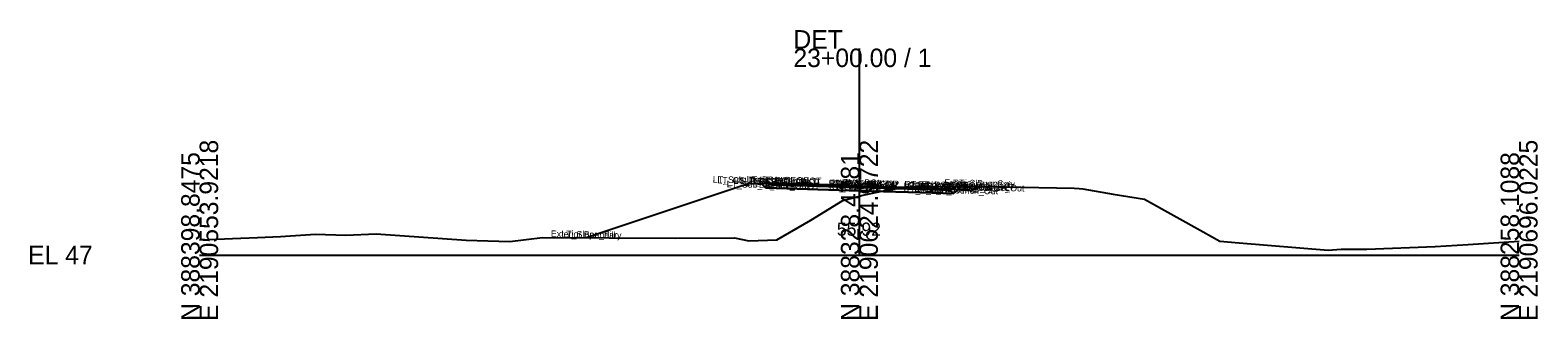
# Model space of a CAD drawing. Extents: x -26 to 1203, y -10 to 9543.
# Drawn here: x 974.3 to 1202.8, y 2990.3 to 3034.1 of the extents above; entities that cross this region are included whole.
import ezdxf

# ---------------------------------------------------------------- set-up
doc = ezdxf.new("R2010")
doc.units = 0
for name, color, linetype in [('Default', 7, 'Continuous'), ('Exist Cross Section Cell', 7, 'Continuous'), ('Exist XS Center Line Elevation Label', 7, 'Continuous'), ('Exist XS Ground Line', 7, 'Continuous'), ('Prop CMT Pvmt Course 1', 7, 'Continuous'), ('Prop CMT Pvmt Course 2', 7, 'Continuous'), ('Prop CMT Pvmt Course 3', 7, 'Continuous'), ('Prop CMT Pvmt Surface', 7, 'Continuous'), ('Prop CMT Pvmt Surface Shoulder', 7, 'Continuous'), ('Prop CMT Shld Paved Course 1', 7, 'Continuous'), ('Prop CMT Shld Paved Course 2', 7, 'Continuous'), ('Prop CMT Shld Paved Course 3', 7, 'Continuous'), ('Prop CMT Slope Grass', 7, 'Continuous'), ('Prop CMT Subgrade Earthwork', 7, 'Continuous'), ('Scratch_Level_0', 7, 'Continuous')]:
    doc.layers.add(name, color=color, linetype=linetype)

msp = doc.modelspace()

# ---------------------------------------------------------------- linework, layer by layer
at = {"layer": 'Exist Cross Section Cell'}
for p, q in [((1100, 3000), (1100, 3031.32)), ((1000, 3000), (1100, 3000)), ((1100, 3000), (1200, 3000))]:
    msp.add_line(p, q, dxfattribs=at)
at = {"layer": 'Exist XS Ground Line'}
for p, q in [((1100.34, 3009.01), (1104.09, 3009.82)), ((1104.09, 3009.82), (1105.8, 3010.08)), ((1105.8, 3010.08), (1107.76, 3010.34)), ((1107.76, 3010.34), (1108.23, 3010.39)), ((1108.23, 3010.39), (1108.58, 3010.42)), ((1108.58, 3010.42), (1109.18, 3010.42)), ((1109.18, 3010.42), (1110.22, 3010.44)), ((1110.22, 3010.44), (1121.06, 3010.36)), ((1121.06, 3010.36), (1121.41, 3010.36)), ((1121.41, 3010.36), (1121.83, 3010.35)), ((1121.83, 3010.35), (1132.55, 3010.14)), ((1132.55, 3010.14), (1133.32, 3010.08)), ((1133.32, 3010.08), (1133.85, 3010.05)), ((1133.85, 3010.05), (1138.49, 3009.22)), ((1092.66, 3005.27), (1097.48, 3008.27)), ((1097.48, 3008.27), (1100, 3008.92)), ((1100, 3008.92), (1100.34, 3009.01)), ((1138.49, 3009.22), (1143.24, 3008.47)), ((1143.24, 3008.47), (1152.12, 3003.54)), ((1087.48, 3002.28), (1092.66, 3005.27)), ((1012.24, 3002.81), (1017.57, 3003.14)), ((1017.57, 3003.14), (1022.17, 3002.99)), ((1022.17, 3002.99), (1026.77, 3003.2)), ((1026.77, 3003.2), (1040.38, 3002.25)), ((1152.12, 3003.54), (1154.66, 3002.1)), ((1000, 3002.29), (1008.78, 3002.68)), ((1008.78, 3002.68), (1012.24, 3002.81)), ((1040.38, 3002.25), (1043.66, 3002.13)), ((1043.66, 3002.13), (1047.02, 3002.03)), ((1047.02, 3002.03), (1051.96, 3002.67)), ((1051.96, 3002.67), (1072.11, 3002.54)), ((1072.11, 3002.54), (1081.08, 3002.61)), ((1081.08, 3002.61), (1083.26, 3002.14)), ((1083.26, 3002.14), (1087.48, 3002.28)), ((1154.66, 3002.1), (1157.56, 3001.86)), ((1157.56, 3001.86), (1171.05, 3000.73)), ((1171.05, 3000.73), (1173.01, 3000.88)), ((1173.01, 3000.88), (1176.92, 3000.88)), ((1176.92, 3000.88), (1187.3, 3001.28)), ((1187.3, 3001.28), (1192.27, 3001.59)), ((1192.27, 3001.59), (1200, 3002.09))]:
    msp.add_line(p, q, dxfattribs=at)
at = {"layer": 'Prop CMT Pvmt Course 1'}
for points in [[(1100, 3010.5), (1089, 3010.83)], [(1089, 3010.83), (1089, 3010.58)], [(1089, 3010.58), (1100, 3010.25)], [(1100, 3010.25), (1100, 3010.5)], [(1100, 3010.5), (1111, 3010.17)], [(1100, 3010.25), (1100, 3010.5)], [(1111, 3009.92), (1100, 3010.25)], [(1111, 3010.17), (1111, 3009.92)]]:
    msp.add_lwpolyline(points, dxfattribs=at)
msp.add_lwpolyline([(1100, 3010.25), (1100, 3010.38), (1100, 3010.38), (1100, 3010.25)], close=True, dxfattribs=at)
msp.add_lwpolyline([(1100, 3010.25), (1100, 3010.38), (1100, 3010.38), (1100, 3010.25)], close=True, dxfattribs=at)
at = {"layer": 'Prop CMT Pvmt Course 2'}
for points in [[(1089, 3010.58), (1100, 3010.25)], [(1100, 3010.25), (1089, 3010.58)], [(1089, 3010.58), (1089, 3010.58)], [(1100, 3010.25), (1100, 3010.25)], [(1111, 3009.92), (1100, 3010.25)], [(1100, 3010.25), (1100, 3010.25)], [(1100, 3010.25), (1111, 3009.92)], [(1111, 3009.92), (1111, 3009.92)]]:
    msp.add_lwpolyline(points, dxfattribs=at)
at = {"layer": 'Prop CMT Pvmt Course 3'}
for points in [[(1100, 3010.25), (1089, 3010.58)], [(1089, 3010.58), (1089, 3010.08)], [(1089, 3010.08), (1100, 3009.75)], [(1100, 3009.75), (1100, 3010.25)], [(1100, 3010.25), (1111, 3009.92)], [(1100, 3009.75), (1100, 3010.25)], [(1111, 3009.92), (1111, 3009.42)], [(1111, 3009.42), (1100, 3009.75)]]:
    msp.add_lwpolyline(points, dxfattribs=at)
at = {"layer": 'Prop CMT Pvmt Surface'}
for points in [[(1100, 3010.5), (1089, 3010.83)], [(1100, 3010.5), (1111, 3010.17)]]:
    msp.add_lwpolyline(points, dxfattribs=at)
at = {"layer": 'Prop CMT Pvmt Surface Shoulder'}
for points in [[(1089, 3010.83), (1087, 3010.89)], [(1111, 3010.17), (1113, 3010.11)]]:
    msp.add_lwpolyline(points, dxfattribs=at)
at = {"layer": 'Prop CMT Shld Paved Course 1'}
for points in [[(1089, 3010.83), (1087, 3010.89), (1086.76, 3010.65)], [(1086.76, 3010.65), (1089, 3010.58)], [(1089, 3010.58), (1089, 3010.83)], [(1111, 3010.17), (1113, 3010.11), (1113.26, 3009.85)], [(1111, 3009.92), (1111, 3010.17)], [(1113.26, 3009.85), (1111, 3009.92)]]:
    msp.add_lwpolyline(points, dxfattribs=at)
at = {"layer": 'Prop CMT Shld Paved Course 2'}
for points in [[(1089, 3010.58), (1086.76, 3010.65)], [(1086.76, 3010.65), (1086.76, 3010.65)], [(1086.76, 3010.65), (1089, 3010.58)], [(1089, 3010.58), (1089, 3010.58)], [(1111, 3009.92), (1113.26, 3009.85)], [(1113.26, 3009.85), (1111, 3009.92)], [(1111, 3009.92), (1111, 3009.92)], [(1113.26, 3009.85), (1113.26, 3009.85)]]:
    msp.add_lwpolyline(points, dxfattribs=at)
at = {"layer": 'Prop CMT Shld Paved Course 3'}
for points in [[(1089, 3010.58), (1086.76, 3010.65), (1086.26, 3010.66), (1085.77, 3010.18)], [(1085.77, 3010.18), (1089, 3010.08)], [(1089, 3010.08), (1089, 3010.58)], [(1111, 3009.92), (1113.26, 3009.85), (1113.76, 3009.84), (1114.27, 3009.32)], [(1111, 3009.42), (1111, 3009.92)], [(1114.27, 3009.32), (1111, 3009.42)]]:
    msp.add_lwpolyline(points, dxfattribs=at)
at = {"layer": 'Prop CMT Slope Grass'}
for points in [[(1087, 3010.89), (1083, 3010.77), (1058.57, 3002.63)], [(1113, 3010.11), (1117, 3009.79), (1117.01, 3009.79), (1118.2, 3010.38)]]:
    msp.add_lwpolyline(points, dxfattribs=at)
at = {"layer": 'Prop CMT Subgrade Earthwork'}
for points in [[(1085.77, 3010.18), (1085.12, 3010.83)], [(1089, 3010.08), (1085.77, 3010.18)], [(1100, 3009.75), (1089, 3010.08)], [(1114.27, 3009.32), (1114.91, 3009.96)], [(1100, 3009.75), (1111, 3009.42)], [(1111, 3009.42), (1114.27, 3009.32)]]:
    msp.add_lwpolyline(points, dxfattribs=at)

# ---------------------------------------------------------------- texts
at = {"layer": 'Default'}
msp.add_text('-', height=0.0001, dxfattribs=at).set_placement((1000, 3000))
at = {"layer": 'Exist Cross Section Cell'}
for s, p in [('DET', (1090, 3031.32)), ('23+00.00 / 1', (1090, 3028.52)), ('EL 47', (974, 2998.6))]:
    msp.add_text(s, height=2.8, dxfattribs=at).set_placement(p)
for s, p in [('E 2190553.9218', (1002.8, 2990)), ('E 2190624.9722', (1102.8, 2990)), ('E 2190696.0225', (1202.8, 2990)), ('N 388398.8475', (1000, 2990)), ('N 388328.4781', (1100, 2990)), ('N 388258.1088', (1200, 2990))]:
    msp.add_text(s, height=2.8, rotation=90, dxfattribs=at).set_placement(p)
at = {"layer": 'Exist XS Center Line Elevation Label'}
msp.add_text('55.92', height=2, dxfattribs=at).set_placement((1096.58, 3002.92))
at = {"layer": 'Scratch_Level_0'}
for s, p in [('LT_Sub_Trench_Out_DLT', (1077.77, 3010.98)), ('LT_GS_OS_CTL', (1078.46, 3010.86)), ('LT_Sub_Trench_Out', (1079.88, 3010.29)), ('LT_PS3_Shelf_Out', (1080.92, 3010.77)), ('LT_PS3_OEOP', (1082.54, 3010.73)), ('LT_PS2_OEOP', (1082.54, 3010.73)), ('LT_PS1_OEOP', (1082.91, 3010.97)), ('LT_PV2_OEOT', (1084.75, 3010.66)), ('LT_PV3_OEOT', (1084.75, 3010.66)), ('LT_Sub_OEOT', (1084.77, 3010.16)), ('LT_PV1_OEOT', (1084.87, 3010.91)), ('RT_PV2_OEEOP', (1095.33, 3010.34)), ('RT_PV3_OEEOP', (1095.33, 3010.34)), ('RT_Sub_OEEOP', (1095.36, 3009.84)), ('LT_PV2_OEEOP', (1095.39, 3010.34)), ('LT_PV3_OEEOP', (1095.39, 3010.34)), ('LT_Sub_OEEOP', (1095.42, 3009.84)), ('RT_PV1_OEEOP', (1095.45, 3010.46)), ('LT_PV1_OEEOP', (1095.51, 3010.46)), ('RT_PV2_IEEOP', (1095.71, 3010.33)), ('LT_PV2_IEEOP', (1095.77, 3010.33)), ('RT_PV1_IEEOP', (1095.83, 3010.46)), ('LT_PV1_IEEOP', (1095.89, 3010.46)), ('PV2_PGL', (1097.35, 3010.3)), ('PV1_PGL', (1097.47, 3010.55)), ('RT_PV3_OEOT', (1106.69, 3010)), ('RT_PV2_OEOT', (1106.69, 3010)), ('RT_Sub_OEOT', (1106.71, 3009.5)), ('RT_PV1_OEOT', (1106.81, 3010.25)), ('RT_Sub_Trench_Out_DLT', (1107.5, 3010.1)), ('RT_Sub_Trench_Out', (1108.32, 3009.44)), ('RT_PS3_Shelf_Out', (1108.36, 3009.94)), ('RT_PS1_OEOP', (1108.85, 3010.19)), ('RT_PS3_OEOP', (1108.99, 3009.94)), ('RT_PS2_OEOP', (1108.99, 3009.94)), ('RT_SS_Ditch_Base_Out', (1110.21, 3009.92)), ('RT_GS_OS_CTL', (1112.41, 3009.88)), ('Exterior Boundary', (1112.86, 3010.49)), ('RT_Slope_Cut', (1114.15, 3010.46)), ('Exterior Boundary', (1053.23, 3002.73)), ('LT_Slope_Fill', (1054.81, 3002.7))]:
    msp.add_text(s, height=1, rotation=358.8836, dxfattribs=at).set_placement(p)

doc.saveas('drawing.dxf')
